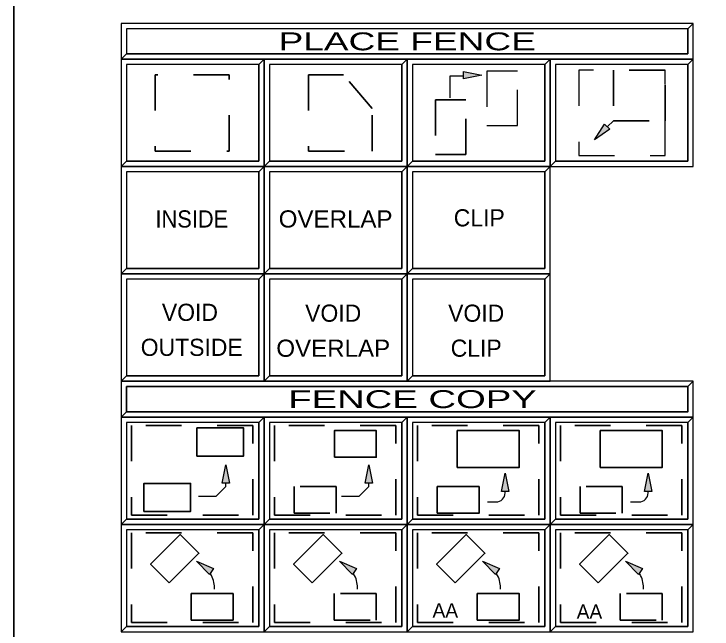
# Model space of a CAD drawing. Extents: x 95906.8 to 95923.6, y 90964.8 to 90972.8.
# Drawn here: x 95906.832 to 95908.785, y 90966.969 to 90968.688 of the extents above; entities that cross this region are included whole.
import ezdxf
from ezdxf.enums import TextEntityAlignment as Align

# ---------------------------------------------------------------- set-up
doc = ezdxf.new("R2010")
doc.units = 0
doc.header["$LTSCALE"] = 0.019
doc.linetypes.add('DOTTED', pattern=[1.5, 0.3, -1.2])
doc.linetypes.add('MEDIUM_DASHED', pattern=[4.5, 3, -1.5])
for name, color, linetype, lineweight in [('1', 7, 'Continuous', 25), ('11', 7, 'Continuous', 25), ('12', 7, 'Continuous', 25), ('18', 7, 'Continuous', 25), ('2', 7, 'Continuous', 13), ('3', 7, 'Continuous', 25), ('6', 7, 'Continuous', 35), ('7', 7, 'Continuous', 35)]:
    doc.layers.add(name, color=color, linetype=linetype, lineweight=lineweight)

msp = doc.modelspace()

# ---------------------------------------------------------------- hatches: boundary and pattern name
at = {"layer": '6'}
for points in [[(95908.1408, 90968.5173), (95908.0896, 90968.5071), (95908.0896, 90968.5275)], [(95908.4558, 90968.3364), (95908.4843, 90968.3801), (95908.4989, 90968.3659)], [(95907.4251, 90967.4281), (95907.4353, 90967.3769), (95907.4149, 90967.3769)], [(95907.8251, 90967.4281), (95907.8353, 90967.3769), (95907.8149, 90967.3769)], [(95908.2059, 90967.4052), (95908.2161, 90967.354), (95908.1957, 90967.354)], [(95908.6059, 90967.4052), (95908.6161, 90967.354), (95908.5957, 90967.354)], [(95907.3426, 90967.1585), (95907.3908, 90967.1384), (95907.3793, 90967.1214)], [(95907.7426, 90967.1585), (95907.7908, 90967.1384), (95907.7793, 90967.1214)], [(95908.1426, 90967.1585), (95908.1908, 90967.1384), (95908.1793, 90967.1214)], [(95908.5426, 90967.1585), (95908.5908, 90967.1384), (95908.5793, 90967.1214)]]:
    msp.add_hatch(color=256, dxfattribs=at).paths.add_polyline_path(points)

# ---------------------------------------------------------------- linework, layer by layer
at = {"layer": '1'}
for points in [[(95907.1323, 90968.5617), (95908.7323, 90968.5617), (95908.7323, 90968.6617), (95907.1323, 90968.6617)], [(95907.1323, 90968.2617), (95907.5323, 90968.2617), (95907.5323, 90968.5617), (95907.1323, 90968.5617)], [(95907.5323, 90968.2617), (95907.9323, 90968.2617), (95907.9323, 90968.5617), (95907.5323, 90968.5617)], [(95907.9323, 90968.2617), (95908.3323, 90968.2617), (95908.3323, 90968.5617), (95907.9323, 90968.5617)], [(95908.3323, 90968.2617), (95908.7323, 90968.2617), (95908.7323, 90968.5617), (95908.3323, 90968.5617)], [(95907.1323, 90967.9617), (95907.5323, 90967.9617), (95907.5323, 90968.2617), (95907.1323, 90968.2617)], [(95907.5323, 90967.9617), (95907.9323, 90967.9617), (95907.9323, 90968.2617), (95907.5323, 90968.2617)], [(95907.9323, 90967.9617), (95908.3323, 90967.9617), (95908.3323, 90968.2617), (95907.9323, 90968.2617)], [(95907.1323, 90967.6617), (95907.5323, 90967.6617), (95907.5323, 90967.9617), (95907.1323, 90967.9617)], [(95907.5323, 90967.6617), (95907.9323, 90967.6617), (95907.9323, 90967.9617), (95907.5323, 90967.9617)], [(95907.9323, 90967.6617), (95908.3323, 90967.6617), (95908.3323, 90967.9617), (95907.9323, 90967.9617)], [(95907.1323, 90967.5617), (95908.7323, 90967.5617), (95908.7323, 90967.6617), (95907.1323, 90967.6617)], [(95907.1323, 90967.2617), (95907.5323, 90967.2617), (95907.5323, 90967.5617), (95907.1323, 90967.5617)], [(95907.5323, 90967.2617), (95907.9323, 90967.2617), (95907.9323, 90967.5617), (95907.5323, 90967.5617)], [(95907.9323, 90967.2617), (95908.3323, 90967.2617), (95908.3323, 90967.5617), (95907.9323, 90967.5617)], [(95908.3323, 90967.2617), (95908.7323, 90967.2617), (95908.7323, 90967.5617), (95908.3323, 90967.5617)], [(95907.1323, 90966.9617), (95907.5323, 90966.9617), (95907.5323, 90967.2617), (95907.1323, 90967.2617)], [(95907.5323, 90966.9617), (95907.9323, 90966.9617), (95907.9323, 90967.2617), (95907.5323, 90967.2617)], [(95907.9323, 90966.9617), (95908.3323, 90966.9617), (95908.3323, 90967.2617), (95907.9323, 90967.2617)], [(95908.3323, 90966.9617), (95908.7323, 90966.9617), (95908.7323, 90967.2617), (95908.3323, 90967.2617)]]:
    msp.add_lwpolyline(points, close=True, dxfattribs=at)
at = {"layer": '11'}
for points in [[(95907.5473, 90968.2767), (95907.9173, 90968.2767), (95907.9173, 90968.5467), (95907.5473, 90968.5467)], [(95907.9473, 90968.2767), (95908.3173, 90968.2767), (95908.3173, 90968.5467), (95907.9473, 90968.5467)], [(95908.3473, 90968.2767), (95908.7173, 90968.2767), (95908.7173, 90968.5467), (95908.3473, 90968.5467)], [(95907.1473, 90967.9767), (95907.5173, 90967.9767), (95907.5173, 90968.2467), (95907.1473, 90968.2467)], [(95907.5473, 90967.9767), (95907.9173, 90967.9767), (95907.9173, 90968.2467), (95907.5473, 90968.2467)], [(95907.9473, 90967.9767), (95908.3173, 90967.9767), (95908.3173, 90968.2467), (95907.9473, 90968.2467)], [(95907.1473, 90967.6767), (95907.5173, 90967.6767), (95907.5173, 90967.9467), (95907.1473, 90967.9467)], [(95907.5473, 90967.6767), (95907.9173, 90967.6767), (95907.9173, 90967.9467), (95907.5473, 90967.9467)], [(95907.9473, 90967.6767), (95908.3173, 90967.6767), (95908.3173, 90967.9467), (95907.9473, 90967.9467)], [(95907.1473, 90967.2767), (95907.5173, 90967.2767), (95907.5173, 90967.5467), (95907.1473, 90967.5467)], [(95907.5473, 90967.2767), (95907.9173, 90967.2767), (95907.9173, 90967.5467), (95907.5473, 90967.5467)], [(95907.9473, 90967.2767), (95908.3173, 90967.2767), (95908.3173, 90967.5467), (95907.9473, 90967.5467)], [(95908.3473, 90967.2767), (95908.7173, 90967.2767), (95908.7173, 90967.5467), (95908.3473, 90967.5467)], [(95907.1473, 90966.9767), (95907.5173, 90966.9767), (95907.5173, 90967.2467), (95907.1473, 90967.2467)], [(95907.5473, 90966.9767), (95907.9173, 90966.9767), (95907.9173, 90967.2467), (95907.5473, 90967.2467)], [(95907.9473, 90966.9767), (95908.3173, 90966.9767), (95908.3173, 90967.2467), (95907.9473, 90967.2467)], [(95908.3473, 90966.9767), (95908.7173, 90966.9767), (95908.7173, 90967.2467), (95908.3473, 90967.2467)]]:
    msp.add_lwpolyline(points, close=True, dxfattribs=at)
at = {"layer": '12'}
msp.add_lwpolyline([(95907.1473, 90968.2767), (95907.5173, 90968.2767), (95907.5173, 90968.5467), (95907.1473, 90968.5467)], close=True, dxfattribs=at)
at = {"layer": '18'}
msp.add_lwpolyline([(95907.1473, 90968.5767), (95908.7173, 90968.5767), (95908.7173, 90968.6467), (95907.1473, 90968.6467)], close=True, dxfattribs=at)
at = {"layer": '18', "lineweight": 35}
msp.add_lwpolyline([(95907.1473, 90967.5767), (95908.7173, 90967.5767), (95908.7173, 90967.6467), (95907.1473, 90967.6467)], close=True, dxfattribs=at)
at = {"layer": '2'}
for points in [[(95907.1323, 90968.6617), (95907.1323, 90968.5617), (95907.1473, 90968.5767), (95907.1473, 90968.6467), (95908.7173, 90968.6467), (95908.7323, 90968.6617)], [(95907.1323, 90968.5617), (95907.1323, 90968.2617), (95907.1473, 90968.2767), (95907.1473, 90968.5467), (95907.5173, 90968.5467), (95907.5323, 90968.5617)], [(95907.5323, 90968.5617), (95907.5323, 90968.2617), (95907.5473, 90968.2767), (95907.5473, 90968.5467), (95907.9173, 90968.5467), (95907.9323, 90968.5617)], [(95907.9323, 90968.5617), (95907.9323, 90968.2617), (95907.9473, 90968.2767), (95907.9473, 90968.5467), (95908.3173, 90968.5467), (95908.3323, 90968.5617)], [(95908.3323, 90968.5617), (95908.3323, 90968.2617), (95908.3473, 90968.2767), (95908.3473, 90968.5467), (95908.7173, 90968.5467), (95908.7323, 90968.5617)], [(95907.1323, 90968.2617), (95907.1323, 90967.9617), (95907.1473, 90967.9767), (95907.1473, 90968.2467), (95907.5173, 90968.2467), (95907.5323, 90968.2617)], [(95907.5323, 90968.2617), (95907.5323, 90967.9617), (95907.5473, 90967.9767), (95907.5473, 90968.2467), (95907.9173, 90968.2467), (95907.9323, 90968.2617)], [(95907.9323, 90968.2617), (95907.9323, 90967.9617), (95907.9473, 90967.9767), (95907.9473, 90968.2467), (95908.3173, 90968.2467), (95908.3323, 90968.2617)], [(95907.1323, 90967.9617), (95907.1323, 90967.6617), (95907.1473, 90967.6767), (95907.1473, 90967.9467), (95907.5173, 90967.9467), (95907.5323, 90967.9617)], [(95907.5323, 90967.9617), (95907.5323, 90967.6617), (95907.5473, 90967.6767), (95907.5473, 90967.9467), (95907.9173, 90967.9467), (95907.9323, 90967.9617)], [(95907.9323, 90967.9617), (95907.9323, 90967.6617), (95907.9473, 90967.6767), (95907.9473, 90967.9467), (95908.3173, 90967.9467), (95908.3323, 90967.9617)], [(95907.1323, 90967.6617), (95907.1323, 90967.5617), (95907.1473, 90967.5767), (95907.1473, 90967.6467), (95908.7173, 90967.6467), (95908.7323, 90967.6617)], [(95907.1323, 90967.5617), (95907.1323, 90967.2617), (95907.1473, 90967.2767), (95907.1473, 90967.5467), (95907.5173, 90967.5467), (95907.5323, 90967.5617)], [(95907.5323, 90967.5617), (95907.5323, 90967.2617), (95907.5473, 90967.2767), (95907.5473, 90967.5467), (95907.9173, 90967.5467), (95907.9323, 90967.5617)], [(95907.9323, 90967.5617), (95907.9323, 90967.2617), (95907.9473, 90967.2767), (95907.9473, 90967.5467), (95908.3173, 90967.5467), (95908.3323, 90967.5617)], [(95908.3323, 90967.5617), (95908.3323, 90967.2617), (95908.3473, 90967.2767), (95908.3473, 90967.5467), (95908.7173, 90967.5467), (95908.7323, 90967.5617)], [(95907.1323, 90967.2617), (95907.1323, 90966.9617), (95907.1473, 90966.9767), (95907.1473, 90967.2467), (95907.5173, 90967.2467), (95907.5323, 90967.2617)], [(95907.5323, 90967.2617), (95907.5323, 90966.9617), (95907.5473, 90966.9767), (95907.5473, 90967.2467), (95907.9173, 90967.2467), (95907.9323, 90967.2617)], [(95907.9323, 90967.2617), (95907.9323, 90966.9617), (95907.9473, 90966.9767), (95907.9473, 90967.2467), (95908.3173, 90967.2467), (95908.3323, 90967.2617)], [(95908.3323, 90967.2617), (95908.3323, 90966.9617), (95908.3473, 90966.9767), (95908.3473, 90967.2467), (95908.7173, 90967.2467), (95908.7323, 90967.2617)]]:
    msp.add_lwpolyline(points, close=True, dxfattribs=at)
at = {"layer": '3'}
for points in [[(95907.1323, 90968.5617), (95908.7323, 90968.5617), (95908.7323, 90968.6617), (95908.7173, 90968.6467), (95908.7173, 90968.5767), (95907.1473, 90968.5767)], [(95907.1323, 90968.2617), (95907.5323, 90968.2617), (95907.5323, 90968.5617), (95907.5173, 90968.5467), (95907.5173, 90968.2767), (95907.1473, 90968.2767)], [(95907.5323, 90968.2617), (95907.9323, 90968.2617), (95907.9323, 90968.5617), (95907.9173, 90968.5467), (95907.9173, 90968.2767), (95907.5473, 90968.2767)], [(95907.9323, 90968.2617), (95908.3323, 90968.2617), (95908.3323, 90968.5617), (95908.3173, 90968.5467), (95908.3173, 90968.2767), (95907.9473, 90968.2767)], [(95908.3323, 90968.2617), (95908.7323, 90968.2617), (95908.7323, 90968.5617), (95908.7173, 90968.5467), (95908.7173, 90968.2767), (95908.3473, 90968.2767)], [(95907.1323, 90967.9617), (95907.5323, 90967.9617), (95907.5323, 90968.2617), (95907.5173, 90968.2467), (95907.5173, 90967.9767), (95907.1473, 90967.9767)], [(95907.5323, 90967.9617), (95907.9323, 90967.9617), (95907.9323, 90968.2617), (95907.9173, 90968.2467), (95907.9173, 90967.9767), (95907.5473, 90967.9767)], [(95907.9323, 90967.9617), (95908.3323, 90967.9617), (95908.3323, 90968.2617), (95908.3173, 90968.2467), (95908.3173, 90967.9767), (95907.9473, 90967.9767)], [(95907.1323, 90967.6617), (95907.5323, 90967.6617), (95907.5323, 90967.9617), (95907.5173, 90967.9467), (95907.5173, 90967.6767), (95907.1473, 90967.6767)], [(95907.5323, 90967.6617), (95907.9323, 90967.6617), (95907.9323, 90967.9617), (95907.9173, 90967.9467), (95907.9173, 90967.6767), (95907.5473, 90967.6767)], [(95907.9323, 90967.6617), (95908.3323, 90967.6617), (95908.3323, 90967.9617), (95908.3173, 90967.9467), (95908.3173, 90967.6767), (95907.9473, 90967.6767)], [(95907.1323, 90967.5617), (95908.7323, 90967.5617), (95908.7323, 90967.6617), (95908.7173, 90967.6467), (95908.7173, 90967.5767), (95907.1473, 90967.5767)], [(95907.1323, 90967.2617), (95907.5323, 90967.2617), (95907.5323, 90967.5617), (95907.5173, 90967.5467), (95907.5173, 90967.2767), (95907.1473, 90967.2767)], [(95907.5323, 90967.2617), (95907.9323, 90967.2617), (95907.9323, 90967.5617), (95907.9173, 90967.5467), (95907.9173, 90967.2767), (95907.5473, 90967.2767)], [(95907.9323, 90967.2617), (95908.3323, 90967.2617), (95908.3323, 90967.5617), (95908.3173, 90967.5467), (95908.3173, 90967.2767), (95907.9473, 90967.2767)], [(95908.3323, 90967.2617), (95908.7323, 90967.2617), (95908.7323, 90967.5617), (95908.7173, 90967.5467), (95908.7173, 90967.2767), (95908.3473, 90967.2767)], [(95907.1323, 90966.9617), (95907.5323, 90966.9617), (95907.5323, 90967.2617), (95907.5173, 90967.2467), (95907.5173, 90966.9767), (95907.1473, 90966.9767)], [(95907.5323, 90966.9617), (95907.9323, 90966.9617), (95907.9323, 90967.2617), (95907.9173, 90967.2467), (95907.9173, 90966.9767), (95907.5473, 90966.9767)], [(95907.9323, 90966.9617), (95908.3323, 90966.9617), (95908.3323, 90967.2617), (95908.3173, 90967.2467), (95908.3173, 90966.9767), (95907.9473, 90966.9767)], [(95908.3323, 90966.9617), (95908.7323, 90966.9617), (95908.7323, 90967.2617), (95908.7173, 90967.2467), (95908.7173, 90966.9767), (95908.3473, 90966.9767)]]:
    msp.add_lwpolyline(points, close=True, dxfattribs=at)
at = {"layer": '6', "lineweight": 25}
for p, q in [((95908.5093, 90968.3899), (95908.4919, 90968.3725)), ((95907.4353, 90967.3769), (95907.4149, 90967.3769)), ((95907.8353, 90967.3769), (95907.8149, 90967.3769)), ((95908.2059, 90967.3495), (95908.2059, 90967.354)), ((95908.6059, 90967.3495), (95908.6059, 90967.354)), ((95908.1569, 90967.3245), (95908.1809, 90967.3245)), ((95908.5569, 90967.3245), (95908.5809, 90967.3245)), ((95907.3933, 90967.081), (95907.3933, 90967.0844)), ((95907.7933, 90967.081), (95907.7933, 90967.0844)), ((95908.1933, 90967.081), (95908.1933, 90967.0844)), ((95908.1933, 90967.081), (95908.1933, 90967.0844)), ((95908.5933, 90967.081), (95908.5933, 90967.0844)), ((95908.5933, 90967.081), (95908.5933, 90967.0844))]:
    msp.add_line(p, q, dxfattribs=at)
for points in [[(95908.1408, 90968.5173), (95908.0896, 90968.5071), (95908.0896, 90968.5275)], [(95908.4558, 90968.3364), (95908.4843, 90968.3801), (95908.4989, 90968.3659)], [(95907.4251, 90967.4281), (95907.4353, 90967.3769), (95907.4149, 90967.3769)], [(95907.8251, 90967.4281), (95907.8353, 90967.3769), (95907.8149, 90967.3769)], [(95908.2059, 90967.4052), (95908.2161, 90967.354), (95908.1957, 90967.354)], [(95908.6059, 90967.4052), (95908.6161, 90967.354), (95908.5957, 90967.354)], [(95907.3426, 90967.1585), (95907.3908, 90967.1384), (95907.3793, 90967.1214)], [(95907.7426, 90967.1585), (95907.7908, 90967.1384), (95907.7793, 90967.1214)], [(95908.1426, 90967.1585), (95908.1908, 90967.1384), (95908.1793, 90967.1214)], [(95908.5426, 90967.1585), (95908.5908, 90967.1384), (95908.5793, 90967.1214)]]:
    msp.add_lwpolyline(points, close=True, dxfattribs=at)
at = {"layer": '6', "linetype": 'MEDIUM_DASHED', "lineweight": 25}
for points in [[(95908.1545, 90968.3764), (95908.2409, 90968.3764), (95908.2409, 90968.5287), (95908.1545, 90968.5287)], [(95908.4119, 90968.2925), (95908.6533, 90968.2925), (95908.6533, 90968.5313), (95908.4119, 90968.5313)]]:
    msp.add_lwpolyline(points, close=True, dxfattribs=at)
at = {"layer": '6', "linetype": 'DOTTED'}
for points in [[(95908.6533, 90968.5313), (95908.5093, 90968.5313), (95908.5093, 90968.3899), (95908.6533, 90968.3899)], [(95907.2274, 90968.305), (95907.4344, 90968.305), (95907.4344, 90968.5184), (95907.2274, 90968.5184)], [(95907.6564, 90968.305), (95907.8344, 90968.305), (95907.8344, 90968.4236), (95907.7536, 90968.5184), (95907.6564, 90968.5184)], [(95908.0112, 90968.2951), (95908.0964, 90968.2951), (95908.0964, 90968.4487), (95908.0112, 90968.4487)], [(95907.5007, 90967.5382), (95907.1606, 90967.5382), (95907.1606, 90967.2878), (95907.5007, 90967.2878)], [(95907.9007, 90967.5382), (95907.5606, 90967.5382), (95907.5606, 90967.2878), (95907.9007, 90967.2878)], [(95908.3007, 90967.5382), (95907.9606, 90967.5382), (95907.9606, 90967.2878), (95908.3007, 90967.2878)], [(95908.7007, 90967.5382), (95908.3606, 90967.5382), (95908.3606, 90967.2878), (95908.7007, 90967.2878)], [(95907.5007, 90967.2382), (95907.1606, 90967.2382), (95907.1606, 90966.9878), (95907.5007, 90966.9878)], [(95907.9007, 90967.2382), (95907.5606, 90967.2382), (95907.5606, 90966.9878), (95907.9007, 90966.9878)], [(95908.3007, 90967.2382), (95907.9606, 90967.2382), (95907.9606, 90966.9878), (95908.3007, 90966.9878)], [(95908.7007, 90967.2382), (95908.3606, 90967.2382), (95908.3606, 90966.9878), (95908.7007, 90966.9878)]]:
    msp.add_lwpolyline(points, close=True, dxfattribs=at)
at = {"layer": '6', "lineweight": 25}
for points in [[(95908.0523, 90968.4538), (95908.0523, 90968.5154), (95908.0896, 90968.5154)], [(95907.3487, 90967.3404), (95907.3982, 90967.3404), (95907.4251, 90967.3673), (95907.4251, 90967.3769)], [(95907.7487, 90967.3404), (95907.7982, 90967.3404), (95907.8251, 90967.3673), (95907.8251, 90967.3769)]]:
    msp.add_lwpolyline(points, dxfattribs=at)
at = {"layer": '6'}
for points in [[(95907.3442, 90967.4528), (95907.4747, 90967.4528), (95907.4747, 90967.5315), (95907.3442, 90967.5315)], [(95907.7284, 90967.4495), (95907.8455, 90967.4495), (95907.8455, 90967.5238), (95907.7284, 90967.5238)], [(95908.0724, 90967.421), (95908.2455, 90967.421), (95908.2455, 90967.5238), (95908.0724, 90967.5238)], [(95908.4724, 90967.421), (95908.6455, 90967.421), (95908.6455, 90967.5238), (95908.4724, 90967.5238)], [(95907.1957, 90967.2977), (95907.3262, 90967.2977), (95907.3262, 90967.3764), (95907.1957, 90967.3764)], [(95908.0161, 90967.2929), (95908.1332, 90967.2929), (95908.1332, 90967.3672), (95908.0161, 90967.3672)], [(95907.2668, 90967.0981), (95907.3496, 90967.1809), (95907.2971, 90967.2334), (95907.2143, 90967.1506)], [(95907.6668, 90967.0981), (95907.7496, 90967.1809), (95907.6971, 90967.2334), (95907.6143, 90967.1506)], [(95908.0668, 90967.0981), (95908.1496, 90967.1809), (95908.0971, 90967.2334), (95908.0143, 90967.1506)], [(95908.4668, 90967.0981), (95908.5496, 90967.1809), (95908.4971, 90967.2334), (95908.4143, 90967.1506)], [(95907.3283, 90966.994), (95907.4454, 90966.994), (95907.4454, 90967.0683), (95907.3283, 90967.0683)], [(95908.1283, 90966.994), (95908.2454, 90966.994), (95908.2454, 90967.0683), (95908.1283, 90967.0683)]]:
    msp.add_lwpolyline(points, close=True, dxfattribs=at)
at = {"layer": '6', "linetype": 'MEDIUM_DASHED'}
for points in [[(95907.6161, 90967.2929), (95907.7332, 90967.2929), (95907.7332, 90967.3672), (95907.6161, 90967.3672)], [(95908.4161, 90967.2929), (95908.5332, 90967.2929), (95908.5332, 90967.3672), (95908.4161, 90967.3672)], [(95907.7283, 90966.994), (95907.8454, 90966.994), (95907.8454, 90967.0683), (95907.7283, 90967.0683)], [(95908.5283, 90966.994), (95908.6454, 90966.994), (95908.6454, 90967.0683), (95908.5283, 90967.0683)]]:
    msp.add_lwpolyline(points, close=True, dxfattribs=at)
at = {"layer": '6', "lineweight": 25}
for centre, radius, start, end in [((95908.1809, 90967.3495), 0.025, 270, 0), ((95908.5809, 90967.3495), 0.025, 270, 0), ((95907.3183, 90967.0844), 0.075, 0, 31.2093), ((95907.7183, 90967.0844), 0.075, 0, 31.2093), ((95908.1183, 90967.0844), 0.075, 0, 31.2093), ((95908.5183, 90967.0844), 0.075, 0, 31.2093)]:
    msp.add_arc(centre, radius, start, end, dxfattribs=at)
at = {"layer": '7'}
msp.add_lwpolyline([(95906.8323, 90972.7617), (95918.8323, 90972.7617), (95918.8323, 90964.7617), (95906.8323, 90964.7617)], close=True, dxfattribs=at)

# ---------------------------------------------------------------- texts
at = {"layer": '6'}
for s, width, p in [('INSIDE', 0.95, (95907.3298, 90968.0914)), ('OVERLAP', 1.05, (95907.732, 90968.0914)), ('OVERLAP', 1.05, (95907.7253, 90967.7301))]:
    msp.add_text(s, height=0.048, dxfattribs=dict(at, width=width)).set_placement(p, align=Align.CENTER)
for s, height, p in [('CLIP', 0.048, (95908.1338, 90968.0945)), ('VOID', 0.048, (95907.3245, 90967.8304)), ('VOID', 0.048, (95907.7252, 90967.8281)), ('VOID', 0.048, (95908.1252, 90967.828)), ('OUTSIDE', 0.048, (95907.3295, 90967.7326)), ('CLIP', 0.048, (95908.1252, 90967.7302)), ('AA', 0.04, (95908.0388, 90967.0012)), ('AA', 0.04, (95908.442, 90966.998))]:
    msp.add_text(s, height=height, dxfattribs=at).set_placement(p, align=Align.CENTER)
at = {"layer": '7'}
for s, width, p in [('      PLACE FENCE      ', 1.55, (95907.9322, 90968.5867)), ('       FENCE COPY      ', 1.6, (95907.9322, 90967.5867))]:
    msp.add_text(s, height=0.04999, dxfattribs=dict(at, width=width)).set_placement(p, align=Align.CENTER)

doc.saveas('drawing.dxf')
